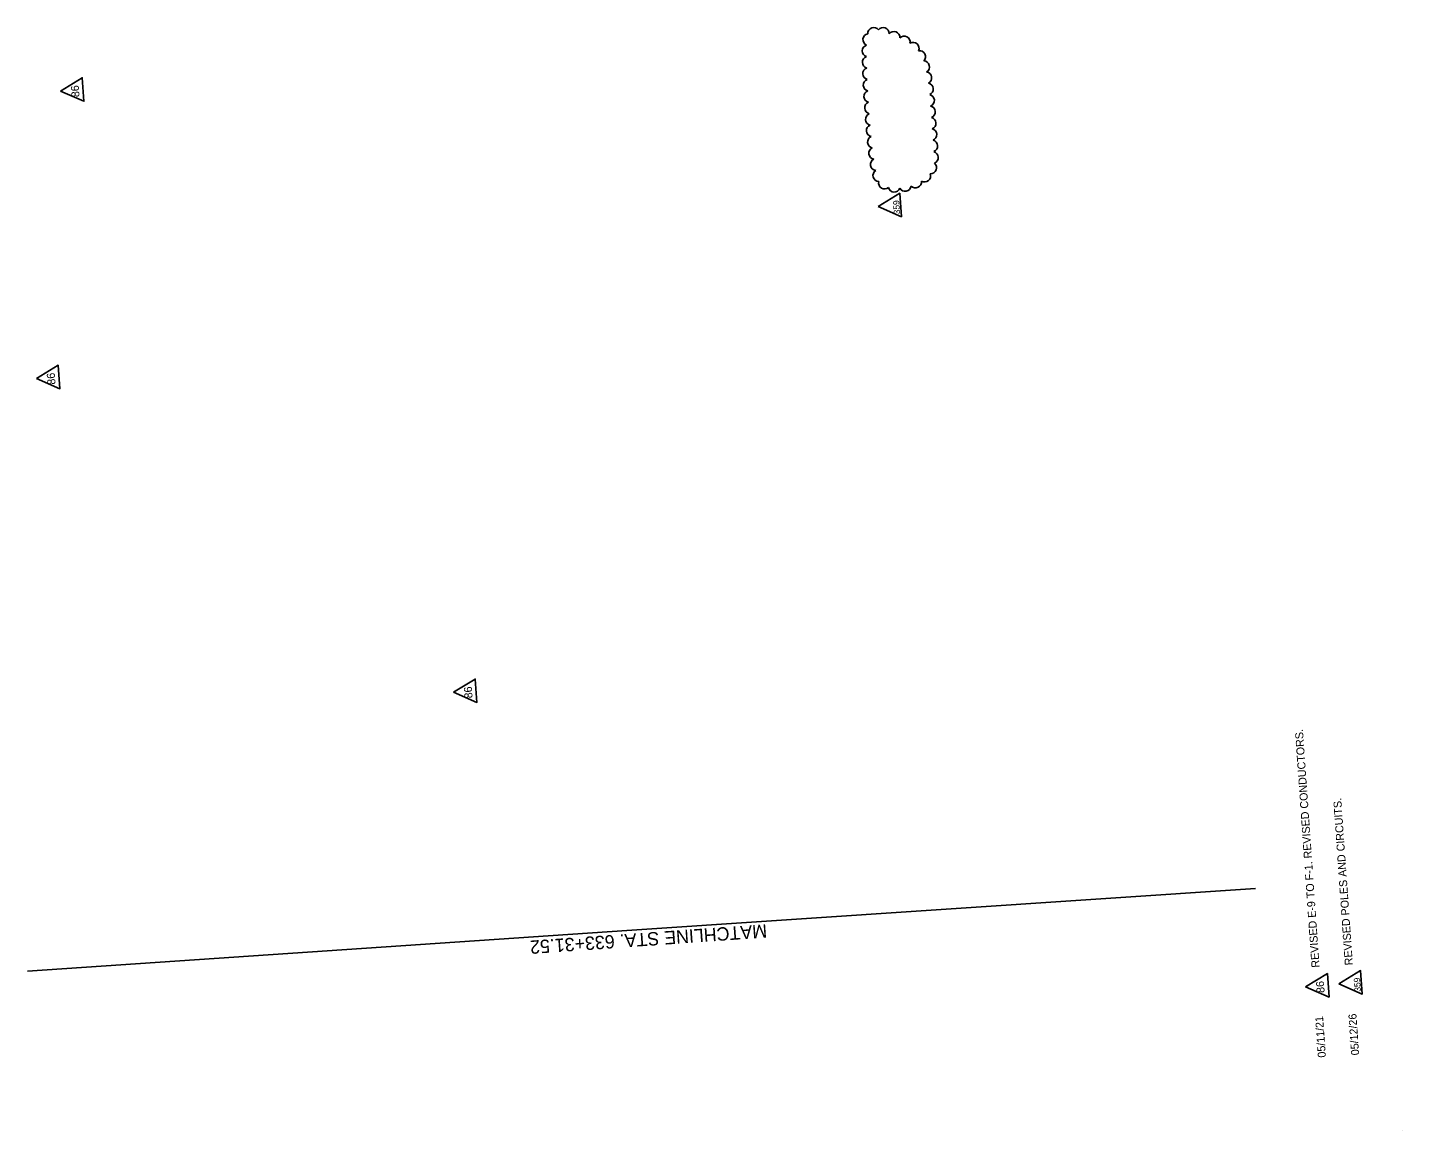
# Model space of a CAD drawing. Extents: x 928662 to 929564, y 639038 to 640295.
# Drawn here: x 928740 to 929564, y 639038 to 639699 of the extents above; entities that cross this region are included whole.
import ezdxf

# ---------------------------------------------------------------- set-up
doc = ezdxf.new("R2010")
doc.units = 0
for name, color, linetype in [('PlotBorder_dp', 7, 'Continuous'), ('ScratchEle_dp', 7, 'Continuous'), ('TextMinor', 7, 'Continuous')]:
    doc.layers.add(name, color=color, linetype=linetype)

msp = doc.modelspace()

# ---------------------------------------------------------------- linework, layer by layer
at = {"layer": 'PlotBorder_dp'}
msp.add_lwpolyline([(929476.31, 639182.66), (929099.34, 639157.53), (928739.97, 639133.06)], dxfattribs=at)
at = {"layer": 'ScratchEle_dp'}
for points in [[(928759.76, 639660.72), (928773.79, 639654.64), (928772.8, 639668.69)], [(929249.98, 639591.5), (929264, 639585.43), (929263.02, 639599.48)], [(928745.35, 639488.34), (928759.37, 639482.27), (928758.39, 639496.32)], [(928995.44, 639300.25), (929009.46, 639294.18), (929008.47, 639308.23)], [(929506.36, 639123.64), (929520.39, 639117.56), (929519.4, 639131.61)], [(929526.31, 639125.4), (929540.33, 639119.32), (929539.35, 639133.37)]]:
    msp.add_lwpolyline(points, close=True, dxfattribs=at)
for centre, radius, start, end in [((929244.51, 639691.56), 3.6, 101.00121, 246.00121), ((929247.41, 639695.27), 3.59, 37.91777, 182.91777), ((929253.07, 639695.25), 3.59, 356.85595, 141.85595), ((929259.51, 639692.87), 3.59, 357.42093, 142.42093), ((929244.1, 639684.83), 3.59, 107.09663, 252.09663), ((929265.6, 639690.12), 3.59, 349.0536, 134.0536), ((929271, 639686.37), 3.59, 336.44541, 121.44541), ((929244.16, 639678.01), 3.59, 108.9267, 253.9267), ((929274.9, 639681.39), 3.59, 314.78184, 99.78184), ((929277.22, 639675.25), 3.59, 301.60517, 86.60517), ((929244.39, 639671.18), 3.59, 109.91714, 254.91714), ((929278.58, 639668.64), 3.59, 296.63128, 81.63128), ((929244.72, 639664.35), 3.59, 110.56232, 255.56232), ((929279.5, 639661.9), 3.59, 293.86107, 78.86107), ((929245.11, 639657.51), 3.59, 111.02556, 256.02556), ((929245.56, 639650.68), 3.59, 111.39485, 256.39485), ((929280.15, 639655.11), 3.59, 292.05713, 77.05713), ((929246.05, 639643.85), 3.59, 111.87739, 256.87739), ((929280.66, 639648.28), 3.59, 291.51956, 76.51956), ((929281.14, 639641.44), 3.59, 291.51956, 76.51956), ((929246.61, 639637.03), 3.59, 112.52713, 257.52713), ((929281.62, 639634.6), 3.59, 291.51956, 76.51956), ((929247.26, 639630.22), 3.59, 113.42025, 258.42025), ((929282.1, 639627.77), 3.59, 291.51956, 76.51956), ((929248.05, 639623.43), 3.59, 114.76058, 259.76058), ((929282.52, 639620.94), 3.59, 290.40029, 75.40029), ((929249.05, 639616.7), 3.59, 117.11892, 262.11892), ((929250.53, 639610.14), 3.59, 123.37709, 268.37709), ((929281.49, 639614.8), 3.59, 265.64843, 50.64843), ((929253.91, 639605.63), 3.59, 165.30878, 310.30878), ((929266.22, 639604.2), 3.59, 208.98392, 353.98392), ((929272.41, 639606.29), 3.59, 223.32698, 8.32698), ((929277.9, 639609.84), 3.59, 237.46395, 22.46395), ((929259.72, 639603.75), 3.59, 193.86536, 338.86536)]:
    msp.add_arc(centre, radius, start, end, dxfattribs=at)
at = {"layer": 'TextMinor'}
msp.add_line((929564.45, 639037.53), (929564.45, 639037.53), dxfattribs=at)

# ---------------------------------------------------------------- texts
at = {"layer": 'PlotBorder_dp'}
msp.add_text('MATCHLINE STA. 633+31.52', height=8, rotation=183.98824, dxfattribs=at).set_placement((929183.12, 639161.24))
at = {"layer": 'ScratchEle_dp'}
for s, height, p in [('86', 4.8, (928771.19, 639657.24)), ('359', 3.8, (929263.27, 639586.96)), ('86', 4.8, (928756.77, 639484.87)), ('86', 4.8, (929006.86, 639296.78)), ('REVISED E-9 TO F-1. REVISED CONDUCTORS.', 4.8, (929514.75, 639135.34)), ('REVISED POLES AND CIRCUITS.', 4.8, (929534.72, 639136.74)), ('86', 4.8, (929517.79, 639120.16)), ('359', 3.8, (929539.55, 639120.86)), ('05/11/21', 4.8, (929518.54, 639081.4)), ('05/12/26', 4.8, (929538.51, 639082.8))]:
    msp.add_text(s, height=height, rotation=94.01956, dxfattribs=at).set_placement(p)

doc.saveas('drawing.dxf')
